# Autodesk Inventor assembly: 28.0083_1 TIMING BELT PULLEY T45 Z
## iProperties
Created: 2007-06
Part Number: 28.0083_1 TIMING BELT PULLEY T45 Z
Document SubType Name: Assembly
Designer: Andy Moles
Author: Andy Moles
